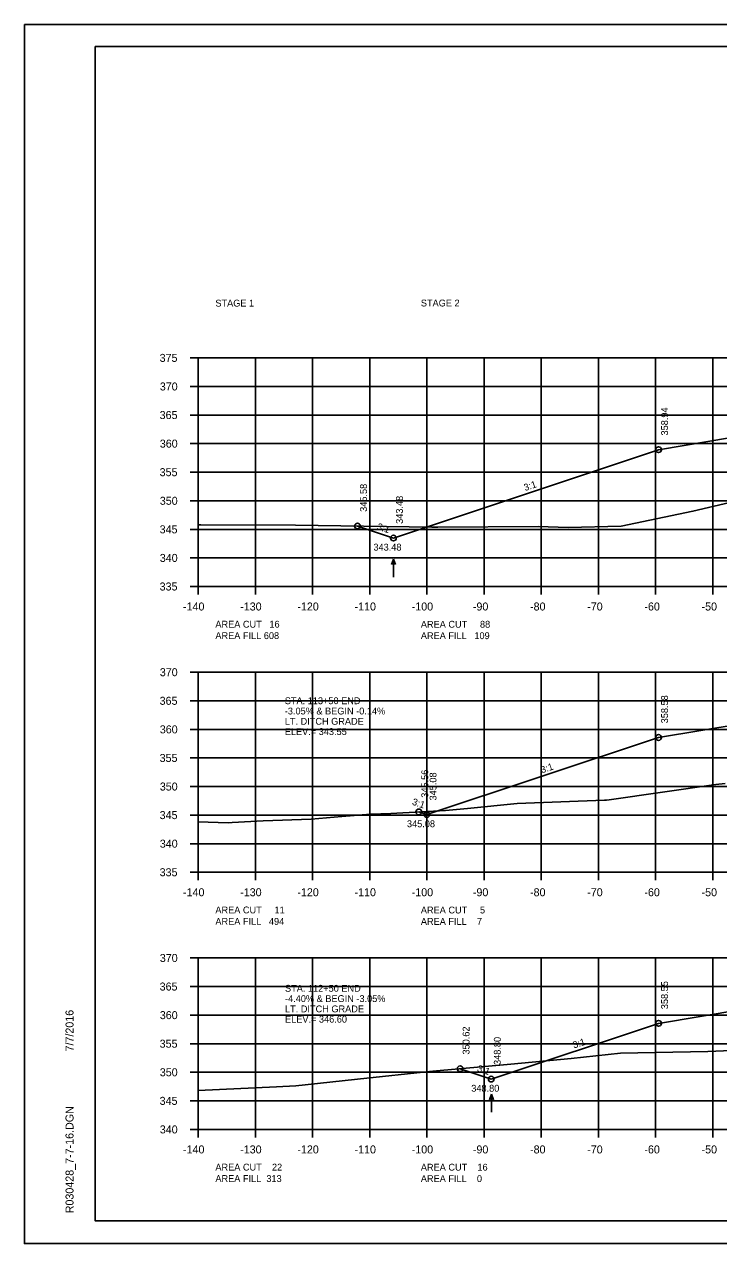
# Model space of a CAD drawing. Extents: x 1374859 to 1376773, y 382242 to 389804.
# Drawn here: x 1376440 to 1376561.5, y 383095.1 to 383308.4 of the extents above; entities that cross this region are included whole.
import ezdxf

# ---------------------------------------------------------------- set-up
doc = ezdxf.new("R2010")
doc.units = 0
for name, color, linetype in [('R_Axis', 7, 'Continuous'), ('R_Axis Annot', 7, 'Continuous'), ('R_Border', 7, 'Continuous'), ('R_Detour Annot', 7, 'Continuous'), ('R_Exist Surface', 7, 'Continuous'), ('R_Fin Surface', 7, 'Continuous'), ('R_Grid', 7, 'Continuous'), ('R_No Plot', 7, 'Continuous'), ('R_Water Annot', 7, 'Continuous'), ('R_Xsect Elev', 7, 'Continuous'), ('R_Xsect Slope', 7, 'Continuous')]:
    doc.layers.add(name, color=color, linetype=linetype)

msp = doc.modelspace()

# ---------------------------------------------------------------- linework, layer by layer
at = {"layer": 'R_Axis'}
for p, q in [((1376469.05, 383250.07), (1376470.45, 383250.07)), ((1376470.45, 383210.07), (1376470.45, 383250.07)), ((1376469.05, 383245.07), (1376470.45, 383245.07)), ((1376469.05, 383240.07), (1376470.45, 383240.07)), ((1376469.05, 383235.07), (1376470.45, 383235.07)), ((1376469.05, 383230.07), (1376470.45, 383230.07)), ((1376469.05, 383225.07), (1376470.45, 383225.07)), ((1376469.05, 383220.07), (1376470.45, 383220.07)), ((1376469.05, 383215.07), (1376470.45, 383215.07)), ((1376469.05, 383210.07), (1376470.45, 383210.07)), ((1376470.45, 383210.07), (1376750.45, 383210.07)), ((1376470.45, 383208.67), (1376470.45, 383210.07)), ((1376480.45, 383208.67), (1376480.45, 383210.07)), ((1376490.45, 383208.67), (1376490.45, 383210.07)), ((1376500.45, 383208.67), (1376500.45, 383210.07)), ((1376510.45, 383208.67), (1376510.45, 383210.07)), ((1376520.45, 383208.67), (1376520.45, 383210.07)), ((1376530.45, 383208.67), (1376530.45, 383210.07)), ((1376540.45, 383208.67), (1376540.45, 383210.07)), ((1376550.45, 383208.67), (1376550.45, 383210.07)), ((1376560.45, 383208.67), (1376560.45, 383210.07)), ((1376469.05, 383195.07), (1376470.45, 383195.07)), ((1376470.45, 383160.07), (1376470.45, 383195.07)), ((1376469.05, 383190.07), (1376470.45, 383190.07)), ((1376469.05, 383185.07), (1376470.45, 383185.07)), ((1376469.05, 383180.07), (1376470.45, 383180.07)), ((1376469.05, 383175.07), (1376470.45, 383175.07)), ((1376469.05, 383170.07), (1376470.45, 383170.07)), ((1376469.05, 383165.07), (1376470.45, 383165.07)), ((1376469.05, 383160.07), (1376470.45, 383160.07)), ((1376470.45, 383160.07), (1376750.45, 383160.07)), ((1376470.45, 383158.67), (1376470.45, 383160.07)), ((1376480.45, 383158.67), (1376480.45, 383160.07)), ((1376490.45, 383158.67), (1376490.45, 383160.07)), ((1376500.45, 383158.67), (1376500.45, 383160.07)), ((1376510.45, 383158.67), (1376510.45, 383160.07)), ((1376520.45, 383158.67), (1376520.45, 383160.07)), ((1376530.45, 383158.67), (1376530.45, 383160.07)), ((1376540.45, 383158.67), (1376540.45, 383160.07)), ((1376550.45, 383158.67), (1376550.45, 383160.07)), ((1376560.45, 383158.67), (1376560.45, 383160.07)), ((1376469.05, 383145.07), (1376470.45, 383145.07)), ((1376470.45, 383115.07), (1376470.45, 383145.07)), ((1376469.05, 383140.07), (1376470.45, 383140.07)), ((1376469.05, 383135.07), (1376470.45, 383135.07)), ((1376469.05, 383130.07), (1376470.45, 383130.07)), ((1376469.05, 383125.07), (1376470.45, 383125.07)), ((1376469.05, 383120.07), (1376470.45, 383120.07)), ((1376469.05, 383115.07), (1376470.45, 383115.07)), ((1376470.45, 383115.07), (1376750.45, 383115.07)), ((1376470.45, 383113.67), (1376470.45, 383115.07)), ((1376480.45, 383113.67), (1376480.45, 383115.07)), ((1376490.45, 383113.67), (1376490.45, 383115.07)), ((1376500.45, 383113.67), (1376500.45, 383115.07)), ((1376510.45, 383113.67), (1376510.45, 383115.07)), ((1376520.45, 383113.67), (1376520.45, 383115.07)), ((1376530.45, 383113.67), (1376530.45, 383115.07)), ((1376540.45, 383113.67), (1376540.45, 383115.07)), ((1376550.45, 383113.67), (1376550.45, 383115.07)), ((1376560.45, 383113.67), (1376560.45, 383115.07))]:
    msp.add_line(p, q, dxfattribs=at)
at = {"layer": 'R_Border'}
for p, q in [((1376452.45, 383304.53), (1376768.63, 383304.53)), ((1376452.45, 383099.07), (1376452.45, 383304.53)), ((1376452.45, 383099.07), (1376452.45, 383099.07)), ((1376768.63, 383099.07), (1376452.45, 383099.07))]:
    msp.add_line(p, q, dxfattribs=at)
at = {"layer": 'R_Exist Surface'}
for points in [[(1376470.45, 383220.86), (1376470.88, 383220.86), (1376487.45, 383220.81), (1376511.34, 383220.45), (1376511.95, 383220.45), (1376512.38, 383220.45), (1376529.91, 383220.54), (1376535.18, 383220.41), (1376544.41, 383220.62), (1376556.98, 383223.24), (1376563.45, 383224.76)], [(1376470.45, 383168.89), (1376475.71, 383168.73), (1376476.41, 383168.77), (1376481.78, 383169.07), (1376490.21, 383169.37), (1376495.58, 383169.84), (1376500.61, 383170.25), (1376504.15, 383170.36), (1376513.69, 383170.88), (1376517.54, 383171.23), (1376526.25, 383172.08), (1376541.51, 383172.67), (1376541.88, 383172.69), (1376542.32, 383172.75), (1376561, 383175.42), (1376562.59, 383175.61)], [(1376470.45, 383121.86), (1376484.12, 383122.54), (1376487.52, 383122.71), (1376499.95, 383124.01), (1376509.77, 383125.07), (1376511.46, 383125.27), (1376525.13, 383126.47), (1376535.66, 383127.47), (1376544.34, 383128.39), (1376559.58, 383128.7), (1376563.73, 383128.88)]]:
    msp.add_lwpolyline(points, dxfattribs=at)
at = {"layer": 'R_Fin Surface'}
for points in [[(1376498.31, 383220.65), (1376504.59, 383218.55), (1376550.97, 383234.01), (1376563.71, 383236.14), (1376572.97, 383237.68), (1376580.97, 383238), (1376610.47, 383239.05), (1376639.97, 383240.09), (1376647.97, 383240.38), (1376659.51, 383238.45), (1376669.97, 383236.71), (1376712.38, 383222.57), (1376725.33, 383226.89)], [(1376509.02, 383170.63), (1376510.46, 383170.15), (1376550.97, 383183.65), (1376565.4, 383186.05), (1376572.97, 383187.32), (1376580.97, 383187.64), (1376610.47, 383188.26), (1376639.97, 383188.89), (1376647.97, 383189.06), (1376658.74, 383187.26), (1376669.97, 383185.39), (1376684.31, 383180.61)], [(1376516.25, 383125.69), (1376521.71, 383123.87), (1376550.97, 383133.63), (1376565.53, 383136.05), (1376572.97, 383137.29), (1376580.97, 383137.61), (1376610.47, 383138.2), (1376639.97, 383138.02), (1376647.97, 383137.98), (1376669.95, 383137.26)]]:
    msp.add_lwpolyline(points, dxfattribs=at)
at = {"layer": 'R_Grid'}
for p, q in [((1376470.45, 383250.07), (1376750.45, 383250.07)), ((1376470.45, 383210.07), (1376470.45, 383250.07)), ((1376480.45, 383210.07), (1376480.45, 383250.07)), ((1376490.45, 383210.07), (1376490.45, 383250.07)), ((1376500.45, 383210.07), (1376500.45, 383250.07)), ((1376510.45, 383210.07), (1376510.45, 383250.07)), ((1376520.45, 383210.07), (1376520.45, 383250.07)), ((1376530.45, 383210.07), (1376530.45, 383250.07)), ((1376540.45, 383210.07), (1376540.45, 383250.07)), ((1376550.45, 383210.07), (1376550.45, 383250.07)), ((1376560.45, 383210.07), (1376560.45, 383250.07)), ((1376470.45, 383245.07), (1376750.45, 383245.07)), ((1376470.45, 383240.07), (1376750.45, 383240.07)), ((1376470.45, 383235.07), (1376750.45, 383235.07)), ((1376470.45, 383230.07), (1376750.45, 383230.07)), ((1376470.45, 383225.07), (1376750.45, 383225.07)), ((1376470.45, 383220.07), (1376750.45, 383220.07)), ((1376470.45, 383215.07), (1376750.45, 383215.07)), ((1376470.45, 383210.07), (1376750.45, 383210.07)), ((1376470.45, 383195.07), (1376750.45, 383195.07)), ((1376470.45, 383160.07), (1376470.45, 383195.07)), ((1376480.45, 383160.07), (1376480.45, 383195.07)), ((1376490.45, 383160.07), (1376490.45, 383195.07)), ((1376500.45, 383160.07), (1376500.45, 383195.07)), ((1376510.45, 383160.07), (1376510.45, 383195.07)), ((1376520.45, 383160.07), (1376520.45, 383195.07)), ((1376530.45, 383160.07), (1376530.45, 383195.07)), ((1376540.45, 383160.07), (1376540.45, 383195.07)), ((1376550.45, 383160.07), (1376550.45, 383195.07)), ((1376560.45, 383160.07), (1376560.45, 383195.07)), ((1376470.45, 383190.07), (1376750.45, 383190.07)), ((1376470.45, 383185.07), (1376750.45, 383185.07)), ((1376470.45, 383180.07), (1376750.45, 383180.07)), ((1376470.45, 383175.07), (1376750.45, 383175.07)), ((1376470.45, 383170.07), (1376750.45, 383170.07)), ((1376470.45, 383165.07), (1376750.45, 383165.07)), ((1376470.45, 383160.07), (1376750.45, 383160.07)), ((1376470.45, 383145.07), (1376750.45, 383145.07)), ((1376470.45, 383115.07), (1376470.45, 383145.07)), ((1376480.45, 383115.07), (1376480.45, 383145.07)), ((1376490.45, 383115.07), (1376490.45, 383145.07)), ((1376500.45, 383115.07), (1376500.45, 383145.07)), ((1376510.45, 383115.07), (1376510.45, 383145.07)), ((1376520.45, 383115.07), (1376520.45, 383145.07)), ((1376530.45, 383115.07), (1376530.45, 383145.07)), ((1376540.45, 383115.07), (1376540.45, 383145.07)), ((1376550.45, 383115.07), (1376550.45, 383145.07)), ((1376560.45, 383115.07), (1376560.45, 383145.07)), ((1376470.45, 383140.07), (1376750.45, 383140.07)), ((1376470.45, 383135.07), (1376750.45, 383135.07)), ((1376470.45, 383130.07), (1376750.45, 383130.07)), ((1376470.45, 383125.07), (1376750.45, 383125.07)), ((1376470.45, 383120.07), (1376750.45, 383120.07)), ((1376470.45, 383115.07), (1376750.45, 383115.07))]:
    msp.add_line(p, q, dxfattribs=at)
at = {"layer": 'R_No Plot'}
for p, q in [((1376440.05, 383308.43), (1376773.38, 383308.43)), ((1376440.05, 383095.09), (1376773.38, 383095.09))]:
    msp.add_line(p, q, dxfattribs=at)
for points in [[(1376440.04, 383308.43), (1376773.38, 383308.43), (1376773.38, 383095.09), (1376440.04, 383095.09)], [(1376686.37, 383304.53), (1376686.37, 383294.65), (1376722.1, 383294.65), (1376722.1, 383291.73), (1376745.3, 383291.73), (1376745.3, 383267.4), (1376768.63, 383267.4), (1376768.63, 383099.07), (1376452.45, 383099.07), (1376452.45, 383304.53)]]:
    msp.add_lwpolyline(points, close=True, dxfattribs=at)
for centre in [(1376550.97, 383234.01), (1376498.31, 383220.65), (1376504.59, 383218.55), (1376550.97, 383183.65), (1376509.02, 383170.63), (1376510.46, 383170.15), (1376510.46, 383170.15), (1376550.97, 383133.63), (1376516.25, 383125.69), (1376521.71, 383123.87)]:
    msp.add_circle(centre, 0.5, dxfattribs=at)
at = {"layer": 'R_Water Annot'}
for p, q in [((1376504.61, 383214.86), (1376504.26, 383213.9)), ((1376504.61, 383211.72), (1376504.61, 383214.86)), ((1376504.61, 383214.86), (1376504.96, 383213.9)), ((1376521.74, 383121.23), (1376521.39, 383120.26)), ((1376521.74, 383118.08), (1376521.74, 383121.23)), ((1376521.74, 383121.23), (1376522.09, 383120.26))]:
    msp.add_line(p, q, dxfattribs=at)

# ---------------------------------------------------------------- texts
at = {"layer": 'R_Axis Annot'}
for s, p in [('STAGE 1', (1376473.45, 383259.05)), ('STAGE 2', (1376509.39, 383259.07))]:
    msp.add_text(s, height=1.2, rotation=360, dxfattribs=at).set_placement(p)
for s, height, p in [('375', 1.4, (1376463.7, 383249.37)), ('370', 1.4, (1376463.73, 383244.37)), ('365', 1.4, (1376463.7, 383239.37)), ('360', 1.4, (1376463.73, 383234.37)), ('355', 1.4, (1376463.7, 383229.37)), ('350', 1.4, (1376463.73, 383224.37)), ('345', 1.4, (1376463.7, 383219.37)), ('340', 1.4, (1376463.73, 383214.37)), ('335', 1.4, (1376463.7, 383209.37)), ('-140', 1.4, (1376467.79, 383205.87)), ('-130', 1.4, (1376477.79, 383205.87)), ('-120', 1.4, (1376487.79, 383205.87)), ('-110', 1.4, (1376497.79, 383205.87)), ('-100', 1.4, (1376507.79, 383205.87)), ('-90', 1.4, (1376518.49, 383205.87)), ('-80', 1.4, (1376528.49, 383205.87)), ('-70', 1.4, (1376538.49, 383205.87)), ('-60', 1.4, (1376548.49, 383205.87)), ('-50', 1.4, (1376558.49, 383205.87)), ('AREA CUT   16', 1.2, (1376473.45, 383202.87)), ('AREA CUT     88', 1.2, (1376509.39, 383202.86)), ('AREA FILL 608', 1.2, (1376473.45, 383200.87)), ('AREA FILL   109', 1.2, (1376509.39, 383200.86)), ('370', 1.4, (1376463.73, 383194.37)), ('365', 1.4, (1376463.7, 383189.37)), ('360', 1.4, (1376463.73, 383184.37)), ('355', 1.4, (1376463.7, 383179.37)), ('350', 1.4, (1376463.73, 383174.37)), ('345', 1.4, (1376463.7, 383169.37)), ('340', 1.4, (1376463.73, 383164.37)), ('335', 1.4, (1376463.7, 383159.37)), ('-140', 1.4, (1376467.79, 383155.87)), ('-130', 1.4, (1376477.79, 383155.87)), ('-120', 1.4, (1376487.79, 383155.87)), ('-110', 1.4, (1376497.79, 383155.87)), ('-100', 1.4, (1376507.79, 383155.87)), ('-90', 1.4, (1376518.49, 383155.87)), ('-80', 1.4, (1376528.49, 383155.87)), ('-70', 1.4, (1376538.49, 383155.87)), ('-60', 1.4, (1376548.49, 383155.87)), ('-50', 1.4, (1376558.49, 383155.87)), ('AREA CUT     11', 1.2, (1376473.45, 383152.87)), ('AREA CUT     5', 1.2, (1376509.39, 383152.86)), ('AREA FILL   494', 1.2, (1376473.45, 383150.87)), ('AREA FILL    7', 1.2, (1376509.39, 383150.86)), ('370', 1.4, (1376463.73, 383144.37)), ('365', 1.4, (1376463.7, 383139.37)), ('360', 1.4, (1376463.73, 383134.37)), ('355', 1.4, (1376463.7, 383129.37)), ('350', 1.4, (1376463.73, 383124.37)), ('345', 1.4, (1376463.7, 383119.37)), ('340', 1.4, (1376463.73, 383114.37)), ('-140', 1.4, (1376467.79, 383110.87)), ('-130', 1.4, (1376477.79, 383110.87)), ('-120', 1.4, (1376487.79, 383110.87)), ('-110', 1.4, (1376497.79, 383110.87)), ('-100', 1.4, (1376507.79, 383110.87)), ('-90', 1.4, (1376518.49, 383110.87)), ('-80', 1.4, (1376528.49, 383110.87)), ('-70', 1.4, (1376538.49, 383110.87)), ('-60', 1.4, (1376548.49, 383110.87)), ('-50', 1.4, (1376558.49, 383110.87)), ('AREA CUT    22', 1.2, (1376473.45, 383107.87)), ('AREA CUT    16', 1.2, (1376509.39, 383107.86)), ('AREA FILL  313', 1.2, (1376473.45, 383105.87)), ('AREA FILL    0', 1.2, (1376509.39, 383105.86))]:
    msp.add_text(s, height=height, dxfattribs=at).set_placement(p)
at = {"layer": 'R_Border'}
for s, p in [('7/7/2016', (1376448.64, 383128.71)), ('R030428_7-7-16.DGN', (1376448.64, 383100.4))]:
    msp.add_text(s, height=1.4, rotation=90, dxfattribs=at).set_placement(p)
at = {"layer": 'R_Detour Annot'}
for s, p in [('STA. 113+50 END', (1376485.59, 383189.48)), ('-3.05% & BEGIN -0.14%', (1376485.59, 383187.68)), ('LT. DITCH GRADE', (1376485.59, 383185.88)), ('ELEV.= 343.55', (1376485.59, 383184.08)), ('STA. 112+50 END', (1376485.63, 383139.16)), ('-4.40% & BEGIN -3.05%', (1376485.63, 383137.36)), ('LT. DITCH GRADE', (1376485.63, 383135.56)), ('ELEV.= 346.60', (1376485.63, 383133.76))]:
    msp.add_text(s, height=1.2, dxfattribs=at).set_placement(p)
at = {"layer": 'R_Xsect Elev'}
for s, p in [('358.94', (1376552.62, 383236.49)), ('345.58', (1376499.96, 383223.13)), ('343.48', (1376506.25, 383221.03)), ('358.58', (1376552.62, 383186.13)), ('345.56', (1376510.68, 383173.11)), ('345.08', (1376512.12, 383172.63)), ('358.55', (1376552.62, 383136.11)), ('350.62', (1376517.9, 383128.17)), ('348.80', (1376523.36, 383126.35))]:
    msp.add_text(s, height=1.2, rotation=90, dxfattribs=at).set_placement(p)
for s, p in [('343.48', (1376501.09, 383216.35)), ('345.08', (1376506.96, 383167.95)), ('348.80', (1376518.21, 383121.67))]:
    msp.add_text(s, height=1.2, dxfattribs=at).set_placement(p)
at = {"layer": 'R_Xsect Slope'}
for rotation, p in [(18.4349, (1376527.62, 383226.76)), (341.5651, (1376501.61, 383220.07)), (18.4349, (1376530.56, 383177.37)), (341.5651, (1376507.76, 383171.92)), (18.4349, (1376536.18, 383129.22)), (341.5651, (1376519.14, 383125.26))]:
    msp.add_text('3:1', height=1.2, rotation=rotation, dxfattribs=at).set_placement(p)

doc.saveas('drawing.dxf')
